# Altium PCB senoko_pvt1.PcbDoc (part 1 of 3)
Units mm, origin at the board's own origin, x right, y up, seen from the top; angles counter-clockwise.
Board outline 124.5 x 41 mm, 4 copper layers (Top Layer, Internal Plane 1, Internal Plane 2, Bottom Layer), stack 1.671 mm thick; 226 components, 139 nets, 1479 pads, 355 vias.
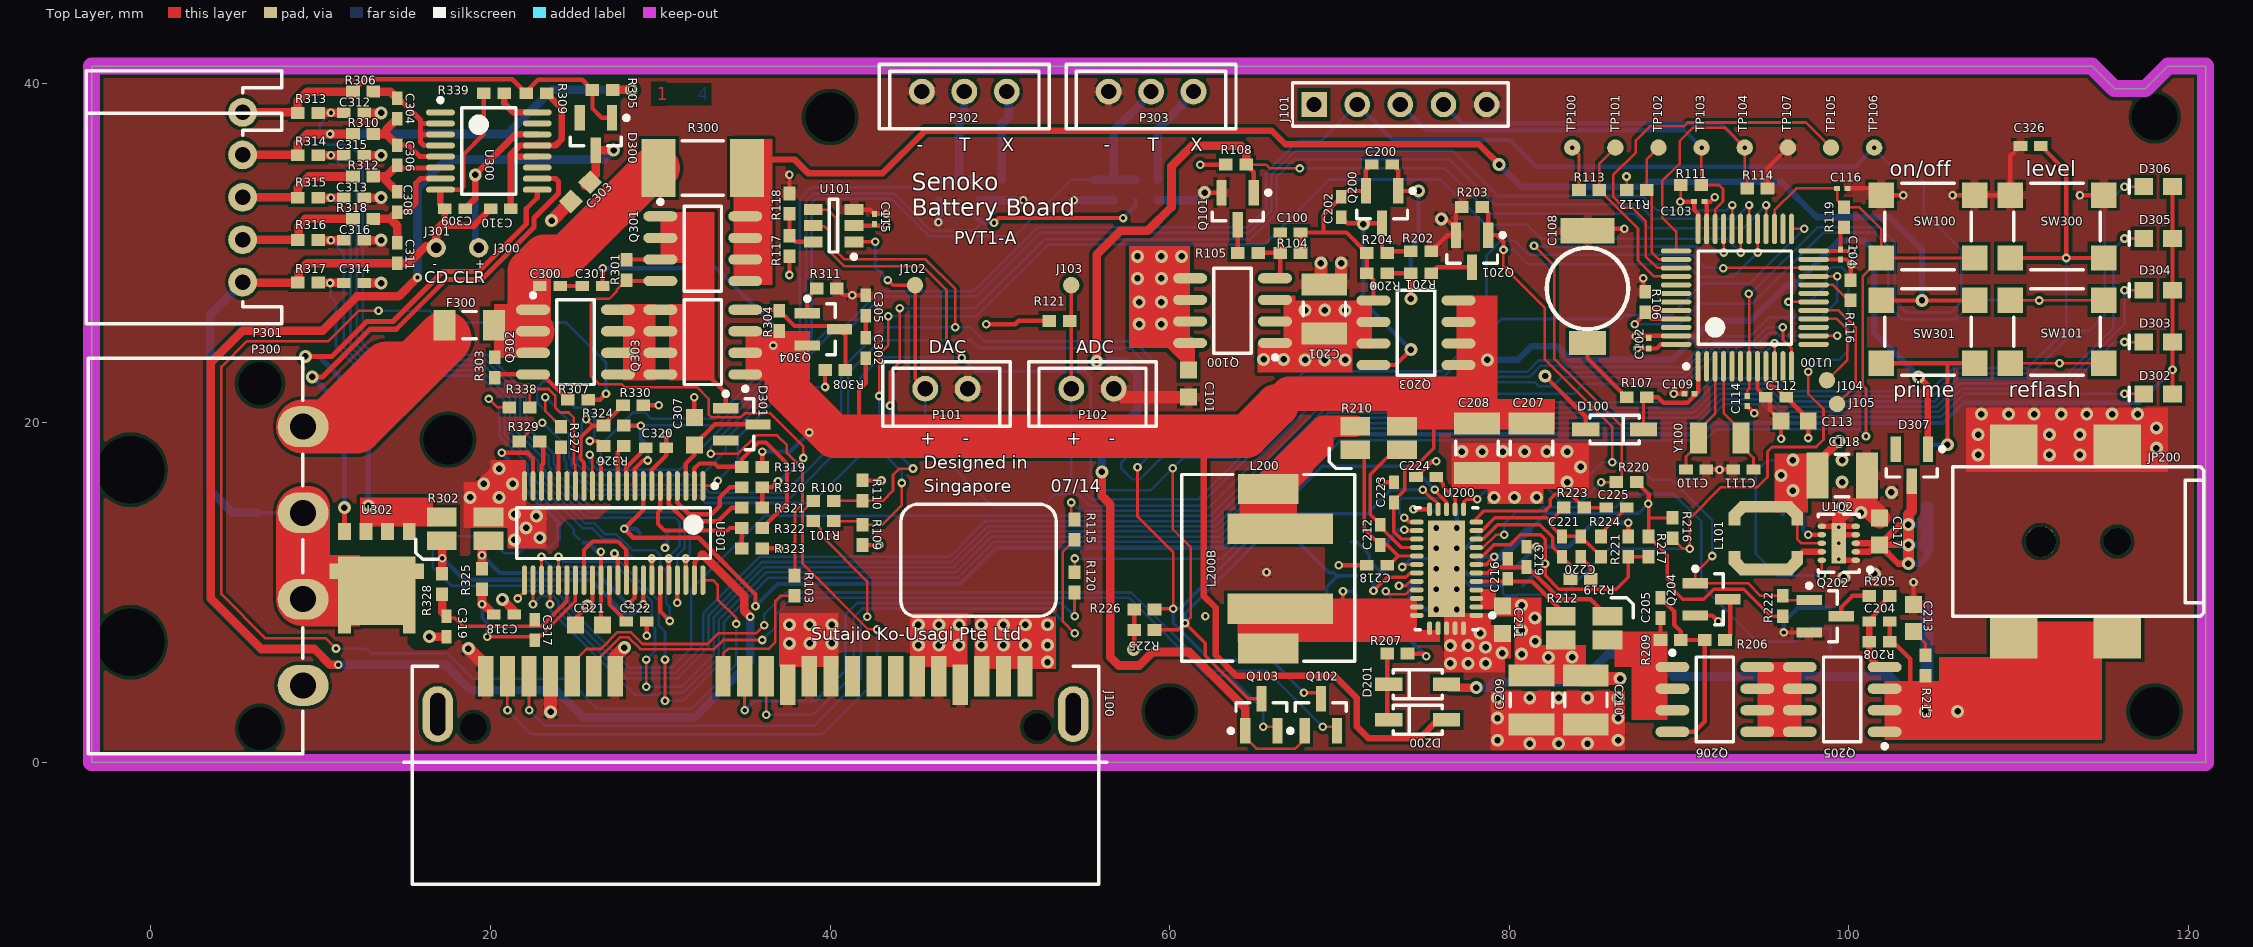
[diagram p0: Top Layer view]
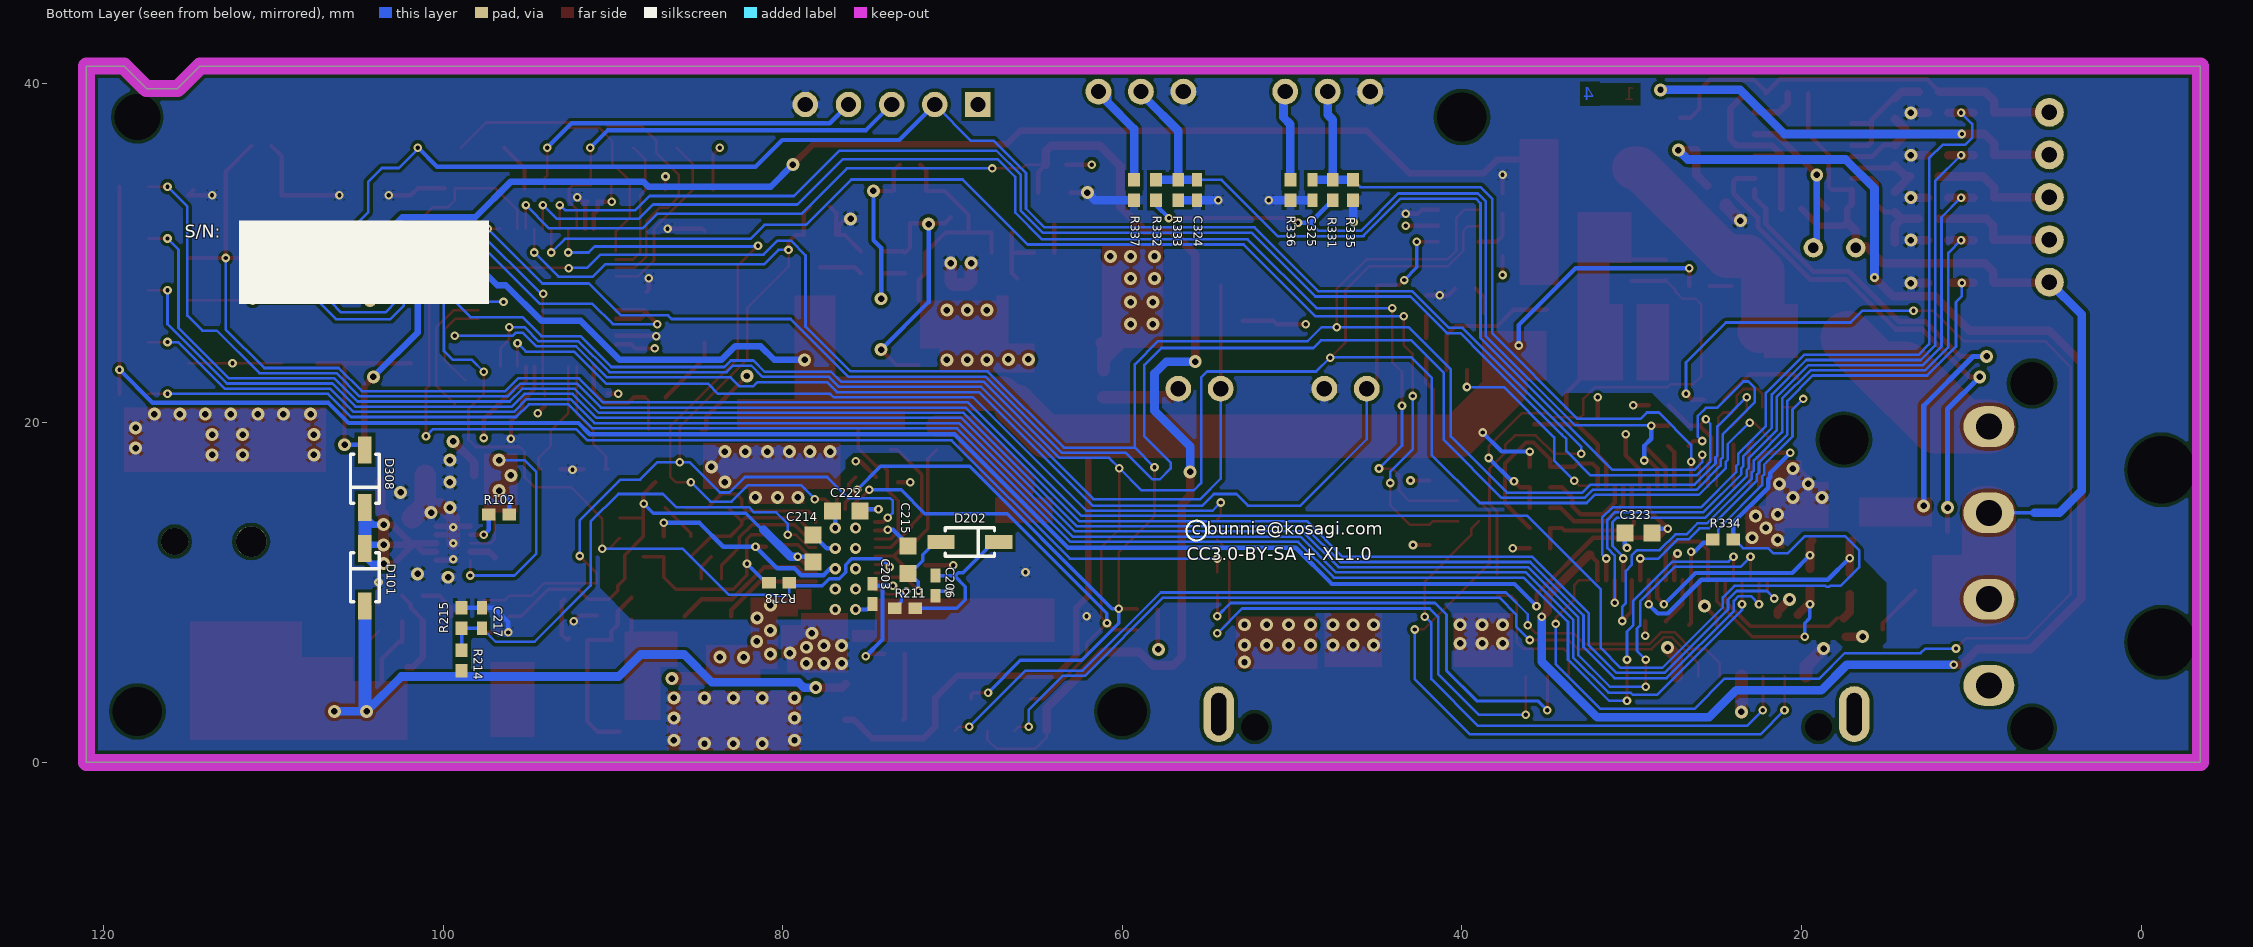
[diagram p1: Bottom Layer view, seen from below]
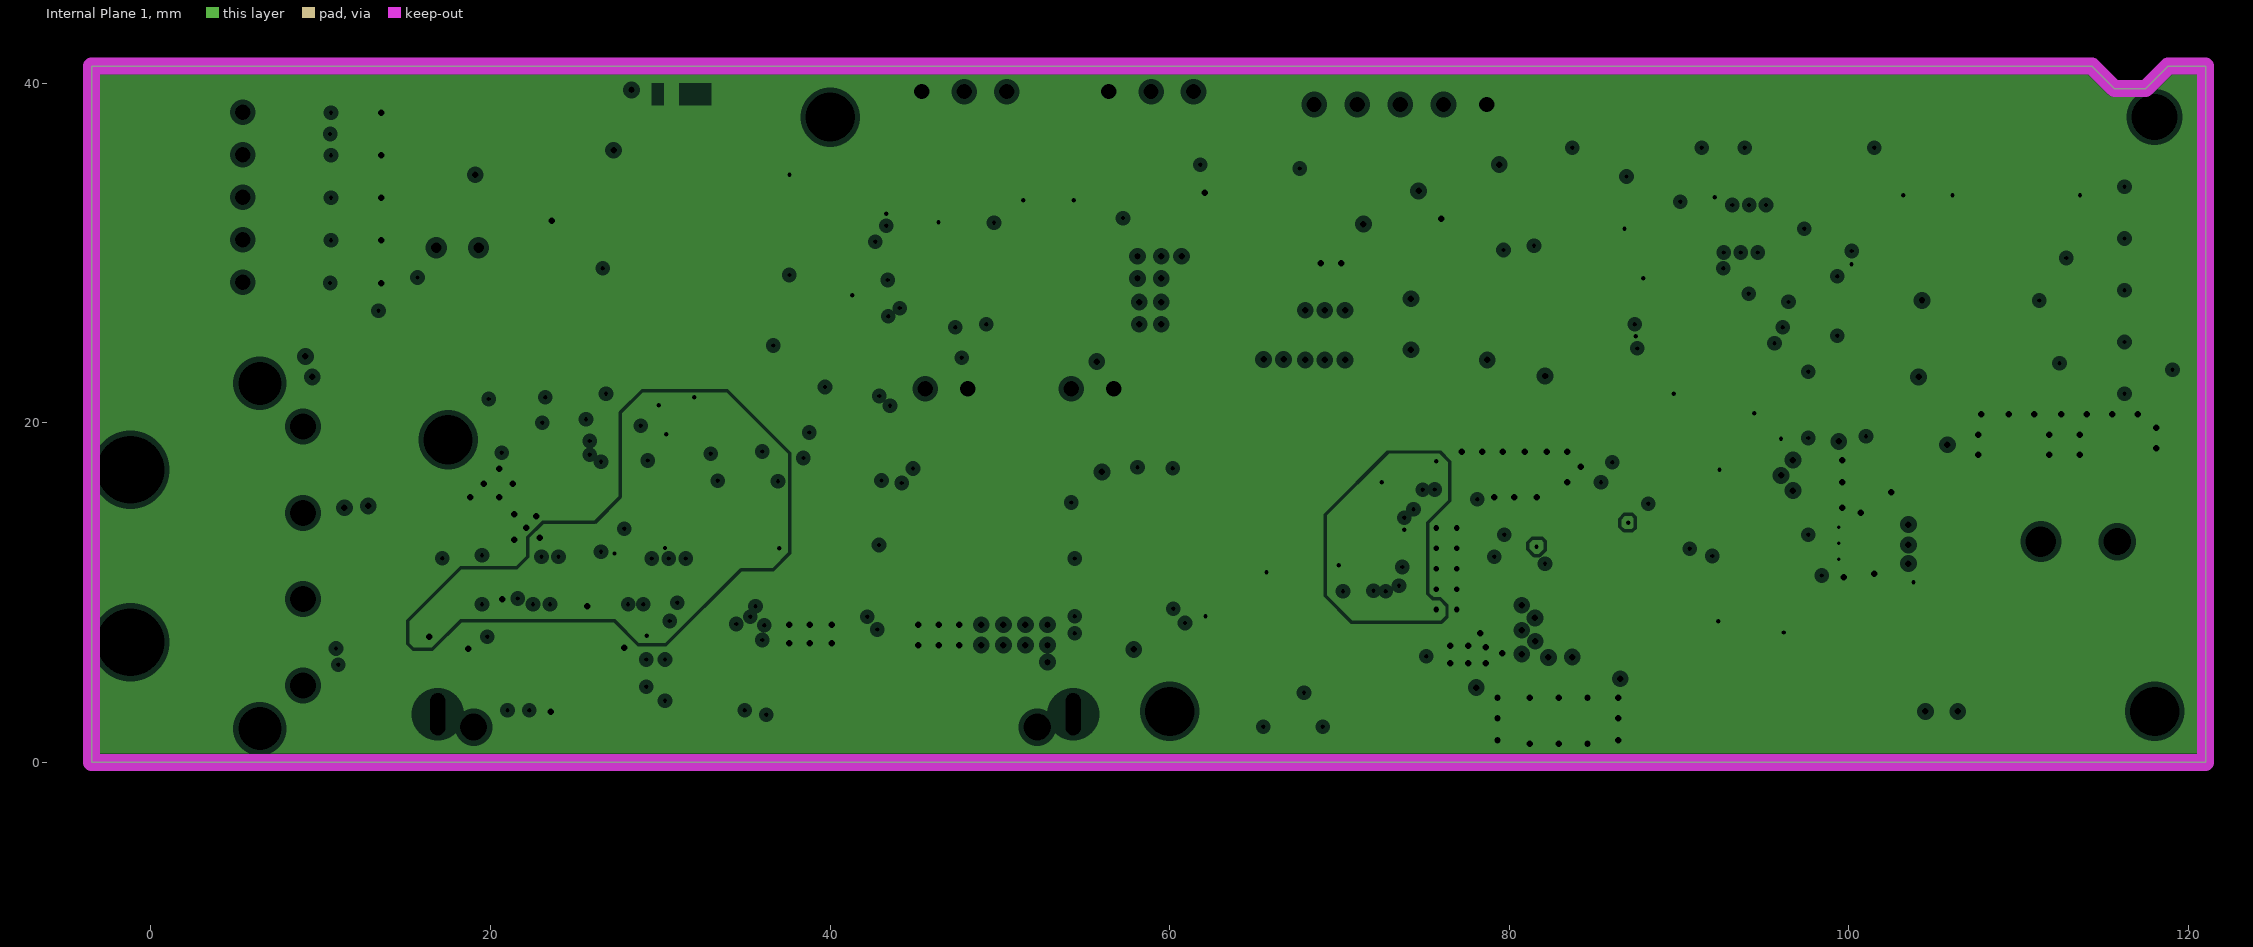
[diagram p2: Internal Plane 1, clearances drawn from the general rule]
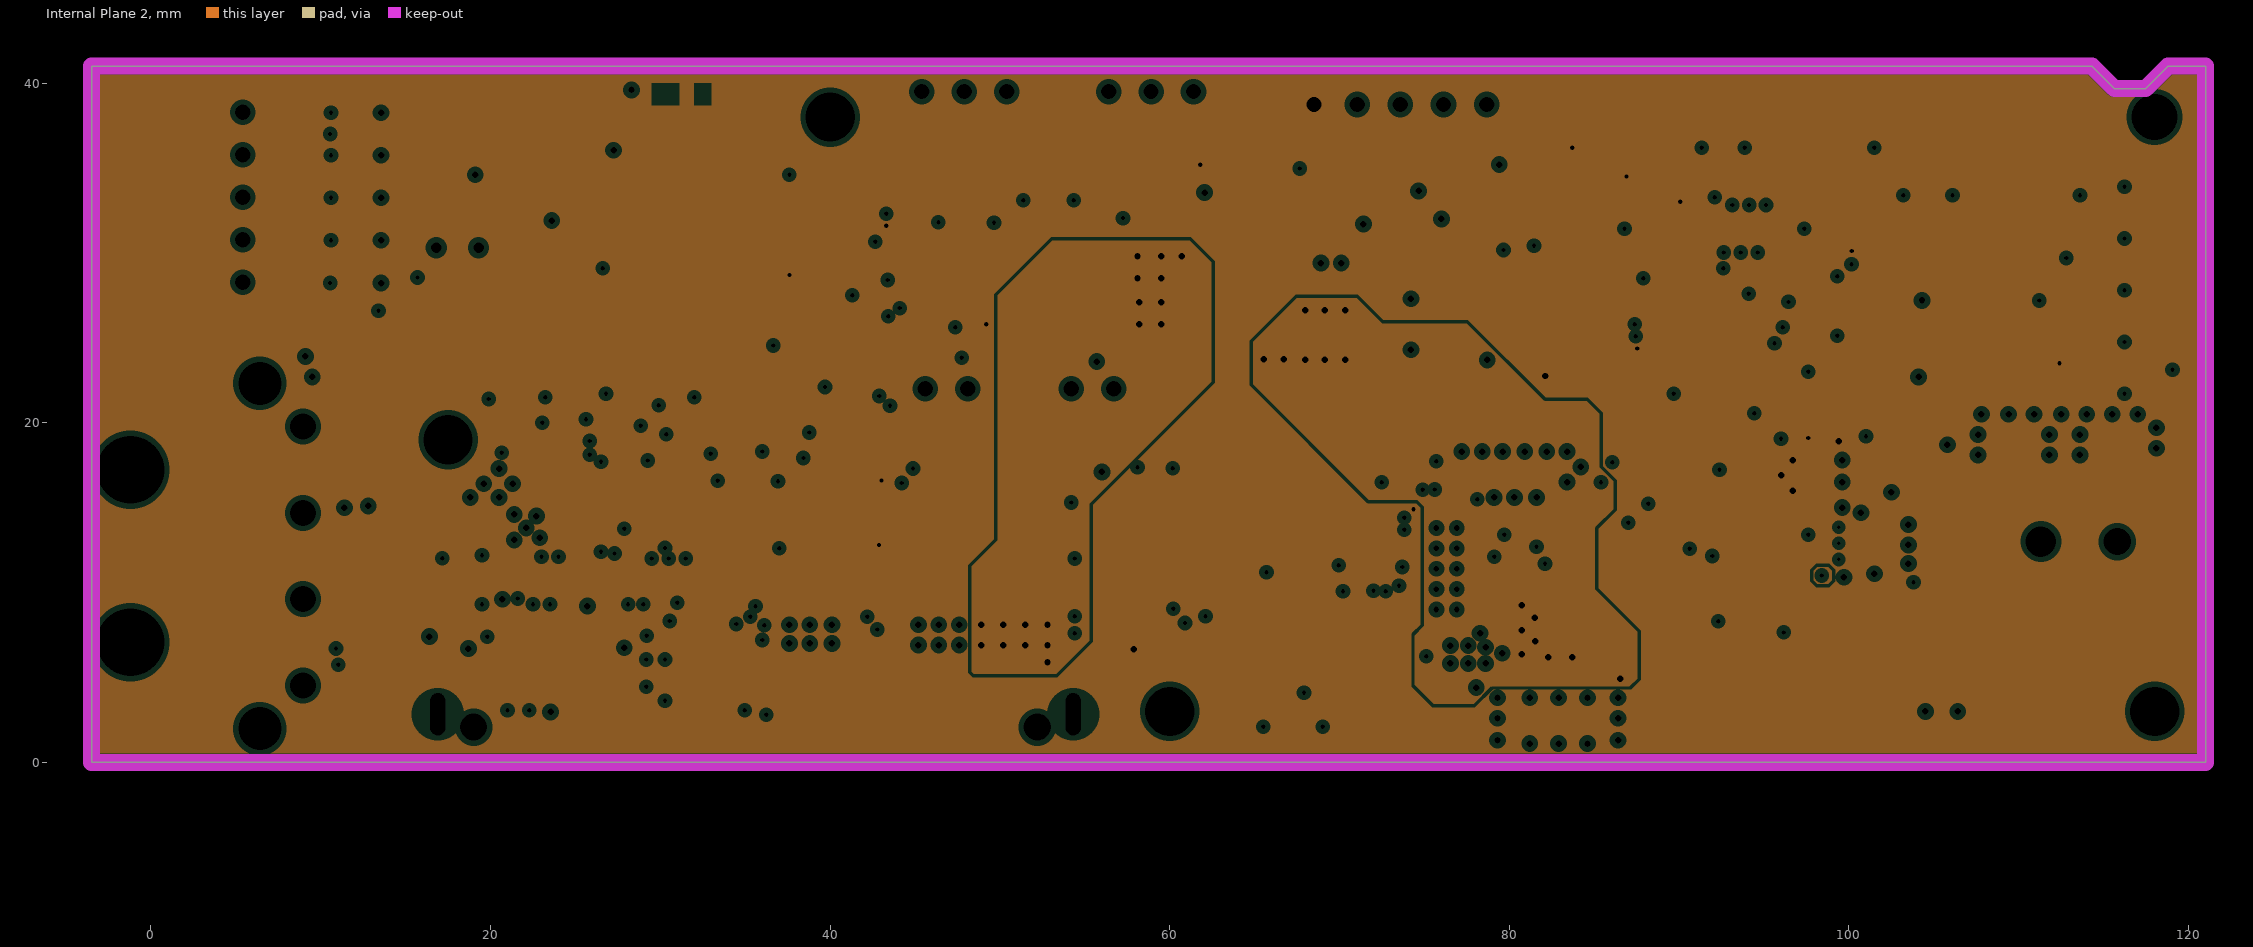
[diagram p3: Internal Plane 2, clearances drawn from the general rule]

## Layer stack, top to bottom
Top Solder: solder mask 0.0102, Solder Resist, Dk 3.5
Top Layer: signal copper 0.0356
Dielectric1: core 0.32, FR-4, Dk 4.8
Internal Plane 1: plane copper 0.0356, net GND
Dielectric2: prepreg 0.889, FR-4, Dk 4.8
Internal Plane 2: plane copper 0.0356, net (Multiple Nets)
Dielectric3: core 0.32, FR-4, Dk 4.8
Bottom Layer: signal copper 0.0356
Bottom Solder: solder mask 0.0102, Solder Resist, Dk 3.5

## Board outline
-3.5,0 -3.5,41 114.3,41 115.625,39.675 117.475,39.675 118.8,41 121,41 121,0

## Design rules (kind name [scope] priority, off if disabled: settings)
Clearance Clearance_poly [InPoly] p1: gap=0.203
Clearance Clearance_NPTH [PadIsPlated = 'False'] p2: gap=0.305
Clearance [All] p3: gap=0.152
ComponentClearance [All] p1 off: gap=0.254 collisioncheckmode=3 verticalgap=0.254 showdistances=FALSE
Height [All] p1 off: minheight=0 maxheight=25.4 prefheight=12.7
HoleSize [All] p1: absolutevalues=TRUE maxlimit=4.445 minlimit=0.025 maxpercent=80.000 minpercent=20.000
MinimumSolderMaskSliver [All] p1 off: minsoldermaskwidth=0.254
PlaneClearance PlaneClearance_M2.5 [(AsMM(HoleSize) = 2.9) or (AsMM(HoleSize) = 2.7)] p1: clearance=1.1
PlaneClearance [All] p2: clearance=0.305
PlaneConnect [All] p1: planeconnectstyle=Direct reliefexpansion=0.508 reliefentries=4 reliefconductorwidth=0.254 reliefairgap=0.254
PolygonConnect [All] p1: connectstyle=Relief reliefconductorwidth=0.508 reliefentries=4 polygonreliefangle="90 Angle" airgapwidth=0.152
RoomDefinition controller [InComponentClass('controller')] p1 off: confinementstyle=ConfineIn formatcopy=TRUE lockcomponents=FALSE outline -1.384,22.5 -3,22.5 -3,30.882 -1.384,30.882
RoomDefinition charger [InComponentClass('charger')] p2 off: confinementstyle=ConfineIn formatcopy=TRUE lockcomponents=FALSE outline -4.586,1.982 -1.8,1.982 -1.8,19 -4.586,19
RoomDefinition battery [InComponentClass('battery')] p3 off: confinementstyle=ConfineIn formatcopy=TRUE lockcomponents=FALSE outline -2.1,25.25 -1.75,25.25 -1.75,0.521 -2.1,0.521
RoutingVias [All] p1: holewidth=0.381 width=0.762 viastyle="Through Hole" minholewidth=0.254 minwidth=0.508 maxholewidth=0.381 maxwidth=0.762
SilkToSilkClearance [All] p1 off: silktosilkclearance=0.254
SilkToSolderMaskClearance SilkscreenOverComponentPads [IsPad] p1 off: minsilkscreentomaskgap=0.254 clearancetoexposedcopper=TRUE
SolderMaskExpansion [All] p1: expansion=0.07
Width [All] p1: maxlimit=5.08 minlimit=0.152 preferedwidth=0.203 minimp=50.000000 maximp=50.000000 favimp=50.000000
21 further rules are at their usual default settings.

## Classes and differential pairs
component class battery: C300 C301 C302 C303 C304 C305 C306 C307 C308 C309 C310 C311 C312 C313 C314 C315 C316 C317 C318 C319 C320 C321 C322 C323 C324 C325 C326 D300 D301 D302 D303 D304 D305 D306 D307 D308 F300 J300 J301 P300 P301 P302 P303 Q301 Q302 Q303 Q304 R300 R301 R302 R303 R304 R305 R306 R307 R308 R309 R310 R311 R312 R313 R314 R315 R316 R317 R318 R319 R320 R321 R322 R323 R324 R325 R326 R327 R328 R329 R330 R331 R332 R333 R334 R335 R336 R337 R338 R339 SW300 SW301 U300 U301 U302
component class charger: C200 C201 C202 C203 C204 C205 C206 C207 C208 C209 C210 C211 C212 C213 C214 C215 C216 C217 C218 C219 C220 C221 C222 C223 C224 C225 D200 D201 D202 JP200 L200 L200B Q200 Q201 Q202 Q203 Q204 Q205 Q206 R200 R201 R202 R203 R204 R205 R206 R207 R208 R209 R210 R211 R212 R213 R214 R215 R216 R217 R218 R219 R220 R221 R222 R223 R224 R225 R226 U200
component class controller: C100 C101 C102 C103 C104 C108 C109 C110 C111 C112 C113 C114 C115 C116 C117 C118 D100 D101 J100 J101 J102 J103 J104 J105 L101 N100 P101 P102 Q100 Q101 Q102 Q103 R100 R101 R102 R103 R104 R105 R106 R107 R108 R109 R110 R111 R112 R113 R114 R115 R116 R117 R118 R119 R120 R121 SW100 SW101 TP100 TP101 TP102 TP103 TP104 TP105 TP106 TP107 U100 U101 U102 Y100

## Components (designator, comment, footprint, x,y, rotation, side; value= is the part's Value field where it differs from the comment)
C100 "10nF, X7R, 50V 10%" CAPC1005N 67.1,31.2 r180 top
C101 "2.2uF, 25V, 10% X5R" CAPC1608N 61.1,22.3 r270 top
C102 "0.1uF, 6.3V, X5R" CAPC0603N_B 88.21,24.677 r90 top
C103 "0.1uF, 6.3V, X5R" CAPC0603N_B 91.18,33.02 r0 top
C104 "0.1uF, 6.3V, X5R" CAPC0603N_B 99.5,29.9 r270 top
C108 "0.06F 3.3V coin supercap" TAIYO_YUDEN_PAS414HR-VA5R 84.6,27.9 r90 top
C109 "0.1uF, 6.3V, X5R" CAPC0603N_B 90.614,21.707 r180 top
C110 "6.8pF, NP0" CAPC1005N 91,17.25 r0 top
C111 "6.8pF, NP0" CAPC1005N 93.775,17.25 r180 top
C112 "10nF, X7R, 50V 10%" CAPC1005N 95.7,21.5 r0 top
C113 "1.0uF, 25V, 20% X5R" CAPC1608N 96.8,20.1 r0 top
C114 "0.1uF, 6.3V, X5R" CAPC0603N_B 94.008,21.282 r270 top
C115 "0.1uF, 6.3V, X5R" CAPC0603N_B 42.6,32 r90 top
C116 "0.1uF, 6.3V, X5R" CAPC0603N_B 99.6,33.8 r180 top
C117 "2.2uF, 25V, 10% X5R" CAPC1608N 101.8,13.6 r90 top
C118 "22uF, 25V, X5R, 10%" CAPC3225N 99.6,16.9 r0 top
C200 "DNP" CAPC1005N 72.5,35.2 r180 top
C201 "22uF, 25V, X5R, 10%" CAPC3225N 69.1,26.7 r90 top
C202 "0.1uF, 25V, X5R" CAPC1005N 70.1,32.7 r270 top
C203 "0.1uF, 25V, X5R" CAPC1005N 74.7,9.925 r270 bottom
C204 "0.1uF, 25V, X5R" CAPC1005N 101.8,8.3 r0 top
C205 "10nF, X7R, 50V 10%" CAPC1005N 88.9,9.1 r270 top
C206 "0.1uF, 25V, X5R" CAPC1005N 71,10.4 r270 bottom
C207 "22uF, 25V, X5R, 10%" CAPC3225N 81.3,18.5 r270 top
C208 "22uF, 25V, X5R, 10% (DNP)" CAPC3225N 78.1,18.5 r270 top
C209 "22uF, 25V, X5R, 10%" CAPC3225N 81.3,3.675 r270 top
C210 "22uF, 25V, X5R, 10% (DNP)" CAPC3225N 84.5,3.675 r270 top
C211 "1.0uF, 25V, 20% X5R" CAPC1608N 79.6,8.4 r270 top
C212 "0.1uF, 25V, X5R" CAPC1005N 72.4,13.4 r270 top
C213 "2.2uF, 25V, 10% X5R" CAPC1608N 103.8,8.5 r90 top
C214 "1.0uF, 25V, 20% X5R" CAPC1608N 78.2,12.6 r90 bottom
C215 "1.0uF, 25V, 20% X5R" CAPC1608N 72.625,11.925 r90 bottom
C216 "0.1uF, 25V, X5R" CAPC1005N 79.9,11.4 r270 top
C217 "10nF, X7R, 50V 10%" CAPC1005N 97.7,8.5 r90 bottom
C218 "0.1uF, 25V, X5R" CAPC1005N 72.2,11.6 r0 top
C219 "0.1uF, 25V, X5R" CAPC1005N 81,12.1 r90 top
C220 "2.2nF, X7R, 10%" CAPC1005N 84.2,12.7 r90 top
C221 "51pF, NP0" CAPC1005N 83.1,12.7 r90 top
C222 "1.0uF, 25V, 20% X5R" CAPC1608N 76.25,14.8 r0 bottom
C223 "0.1uF, 25V, X5R" CAPC1005N 73.2,15.9 r270 top
C224 "100pF, NP0" CAPC1005N 75.1,16.8 r180 top
C225 "130pF, NP0" CAPC1005N 86.3,15 r180 top
C300 "0.1uF, 25V, X5R" CAPC1005N 23.5,28.05 r180 top
C301 "0.1uF, 25V, X5R" CAPC1005N 26,28.05 r180 top
C302 "0.1uF, 25V, X5R" CAPC1005N 42.1,24.4 r270 top
C303 "1.0uF, 25V, 20% X5R" CAPC1608N 25.3,33.6 r225 top
C304 "0.1uF, 25V, X5R" CAPC1005N 14.5,38.5 r270 top
C305 "0.1uF, 25V, X5R" CAPC1005N 42.1,26.9 r270 top
C306 "0.1uF, 25V, X5R" CAPC1005N 14.5,35.75 r270 top
C307 "1.0uF, 25V, 20% X5R" CAPC1608N 32,19.5 r90 top
C308 "0.1uF, 25V, X5R" CAPC1005N 14.5,33 r270 top
C309 "0.22uF, 25V, X5R" CAPC1005N 17.9,32.6 r180 top
C310 "0.1uF, 25V, X5R" CAPC1005N 20.6,32.6 r180 top
C311 "0.1uF, 25V, X5R" CAPC1005N 14.5,30 r270 top
C312 "0.1uF, 25V, X5R" CAPC1005N 11.95,38.25 r0 top
C313 "0.1uF, 25V, X5R" CAPC1005N 11.95,33.25 r0 top
C314 "0.1uF, 25V, X5R" CAPC1005N 11.95,28.225 r0 top
C315 "0.1uF, 25V, X5R" CAPC1005N 11.95,35.75 r0 top
C316 "0.1uF, 25V, X5R" CAPC1005N 11.95,30.75 r0 top
C317 "0.1uF, 25V, X5R" CAPC1005N 22.6,7.8 r90 top
C318 "0.1uF, 25V, X5R" CAPC1005N 20.8,8.7 r0 top
C319 "0.1uF, 25V, X5R" CAPC1005N 17.4,8 r270 top
C320 "0.1uF, 25V, X5R" CAPC1005N 29.75,18.525 r0 top
C321 "1.0uF, 25V, 20% X5R" CAPC1608N 25.8,8.1 r180 top
C322 "0.1uF, 25V, X5R" CAPC1005N 28.6,8.3 r0 top
C323 "10uF, 10V, X5R, 20%" CAPC1608N 29.6,13.5 r0 bottom
C324 "0.47uF, 16V, X5R" CAPC1005N 55.6,33.7 r270 bottom
C325 "0.47uF, 16V, X5R" CAPC1005N 48.8,33.7 r270 bottom
C326 "0.1uF, 25V, X5R" CAPC1005N 110.7,36.3 r180 top
D100 "BAT54T1G" SOD123 86.2,19.6 r0 top
D101 "BAT54T1G" SOD123 104.6,10.9 r90 bottom
D200 "BAT54T1G" SOD123 74.6,2.5 r180 top
D201 "BAT54T1G" SOD123 74.6,4.6 r180 top
D202 "BAT54T1G" SOD123 68.975,12.975 r180 bottom
D300 "BAS16" SOT23-3N 26.2,37 r270 top
D301 "BAS16" SOT23-3N 34.8,19.9 r0 top
D302 "APT1608SGC green" CD1608-0603 118.2,21.7 r180 top
D303 "APT1608SGC green" CD1608-0603 118.2,24.75 r180 top
D304 "APT1608SGC green" CD1608-0603 118.2,27.8 r180 top
D305 "APT1608SGC green" CD1608-0603 118.2,30.85 r180 top
D306 "APT1608SGC green" CD1608-0603 118.2,33.9 r180 top
D307 "BAS16" SOT23-3N 103.7,17.5 r270 top
D308 "BAT54T1G" SOD123 104.6,16.7 r270 bottom
F300 "Littlefuse 0437007.WR 7A 35V Fast Blow" RESC3216N 18.75,25.75 r0 top
J100 "MOLEX 47018-2000 female" SATA_MOLEX_47018_2000 35.6,2.075 r0 top
J101 "Male 2.54mm 5x1 header (DNP)" HDR1X5 68.5,38.74 r0 top
J102 "test point (DNP)" TP_SMT_38mil 45,28.1 r90 top
J103 "test point (DNP)" TP_SMT_38mil 54.2,28.1 r90 top
J104 "test point (DNP)" TP_SMT_38mil 98.7,22.5 r180 top
J105 "test point (DNP)" TP_SMT_38mil 99.3,21.1 r180 top
J300 "test point (DNP)" TP_HOLE 19.3,30.3 r90 top
J301 "test point (DNP)" TP_HOLE 16.8,30.3 r90 top
JP200 "2.1mm x 5.5mm DC jack" CUI_PJ_002AH_SMT 111.3,13 r180 top
L101 "10uH LPS4018-103" COILCRAFT_LPS4018 95.1,13.2 r90 top
L200 "3.3uH, MSS1260-332NL (DNP)" COILCRAFT_MSS1048 65.8,6.7 r0 top
L200B "3.3uH, XAL7030-322MEC" COILCRAFT_XAL7030 66.5,11.4 r90 top
P101 "JST B2B-EH-A" JST_B2B_EH_A 45.6,22 r0 top
P102 "JST B2B-EH-A" JST_B2B_EH_A 54.2,22 r0 top
P300 "Molex 15-24-4441" MOLEX_15-24-4441 -1.2,12.15 r90 top
P301 "JST S4B-XH-A" JST_S5B-XH-A_OPT4 5.4,34.525 r90 top
P302 "JST B3B-EH-A" JST_B3B_EH_A 45.4,39.5 r0 top
P303 "JST B3B-EH-A" JST_B3B_EH_A 56.4,39.5 r0 top
Q100 "Si4435DY" SOIC127P600-8AN 63.7,26.6 r180 top
Q101 "BSS138" SOT23-3N 64,32.6 r270 top
Q102 "BSS138" SOT23-3N 68.9,2.8 r90 top
Q103 "BSS138" SOT23-3N 65.4,2.8 r90 top
Q200 "FDN304P" SOT23-3N 72.5,32.7 r270 top
Q201 "BSS138" SOT23-3N 77.8,30.1 r270 top
Q202 "BSS138" SOT23-3N 98.6,8.6 r0 top
Q203 "Si4435DY" SOIC127P600-8AN 74.5,25.3 r0 top
Q204 "BSS138" SOT23-3N 91.9,9.6 r0 top
Q205 "Si4435DY" SOIC127P600-8AN 99.6,3.7 r180 top
Q206 "Si4435DY" SOIC127P600-8AN 92.1,3.7 r0 top
Q301 "Si4435DY" SOIC127P600-8AN 32.5,30.25 r0 top
Q302 "FDS6690A" SOIC127P600-8AN 25,24.75 r0 top
Q303 "FDS6690A" SOIC127P600-8AN 32.5,24.75 r180 top
Q304 "BSS138" SOT23-3N 39.6,25.5 r0 top
R100 "330, 1%" RESC1005N 39.6,15.4 r180 top
R101 "330, 1%" RESC1005N 39.6,14.2 r180 top
R102 "100k, 1%" RESC1005N 96.7,14.6 r0 bottom
R103 "330, 1%" RESC1005N 37.9,10.4 r270 top
R104 "10k, 1%" RESC1005N 67.1,30 r0 top
R105 "10k, 1%" RESC1005N 64.6,30 r0 top
R106 "47k, 1%" RESC1005N 88,27.1 r270 top
R107 "1k, 1%" RESC1005N 87.5,21.5 r0 top
R108 "100k, 1%" RESC1005N 63.9,35.2 r0 top
R109 "47k, 1%" RESC1005N 41.9,13.4 r270 top
R110 "47k, 1%" RESC1005N 41.9,16 r90 top
R111 "10k, 1%" RESC1005N 90.7,34 r180 top
R112 "10k, 1%" RESC1005N 87.5,33.7 r180 top
R113 "10k, 1%" RESC1005N 84.7,33.7 r180 top
R114 "10k, 1%" RESC1005N 94.6,33.8 r180 top
R115 "330, 1%" RESC1005N 54.4,13.7 r270 top
R116 "10k, 1%" RESC1005N 100.1,27.8 r270 top
R117 "10k, 1% (DNP)" RESC1005N 37.6,30.4 r90 top
R118 "10k, 1%" RESC1005N 37.6,32.9 r90 top
R119 "47k, 1%" RESC1005N 99.7,32.1 r270 top
R120 "330, 1%" RESC1005N 54.4,10.6 r270 top
R121 "4.7k, 1%" RESC1005N 53.5,26 r180 top
R200 "10k, 1%" RESC1005N 72.2,28.8 r0 top
R201 "20k, 1%" RESC1005N 74.8,28.8 r0 top
R202 "100k, 1%" RESC1005N 74.8,30.1 r0 top
R203 "1M, 1%" RESC1005N 77.8,32.7 r0 top
R204 "100k, 1%" RESC1005N 72.2,30 r0 top
R205 "10k, 1%" RESC1005N 101.8,9.8 r180 top
R206 "10k, 1%" RESC1005N 92.1,7.2 r180 top
R207 "10 ohm, 1%" RESC1005N 73.4,6.4 r0 top
R208 "10k, 1%" RESC1005N 101.8,7.1 r180 top
R209 "10k, 1%" RESC1005N 89.5,7.2 r0 top
R210 "0.010 ohm, 1% kelvin, 50ppm" OHMITE_LVK_1206_KELVIN 72.3,19.1 r0 top
R211 "3.9 ohm, 5%" RESC1005N 72.8,9.075 r180 bottom
R212 "0.010 ohm, 1% kelvin, 50ppm" OHMITE_LVK_1206_KELVIN 84.4,7.9 r180 top
R213 "3.9 ohm, 5%" RESC1005N 104.5,5.7 r90 top
R214 "316k, 1%" RESC1005N 98.9,6 r90 bottom
R215 "66.5k, 1%" RESC1005N 98.9,8.5 r90 bottom
R216 "10k, 1%" RESC1005N 89.6,13.8 r270 top
R217 "200k, 1%" RESC1005N 88.2,12.7 r270 top
R218 "1.4M, 1%" RESC1005N 80.2,10.575 r180 bottom
R219 "7.5k, 1%" RESC1005N 84.2,10.8 r180 top
R220 "10k, 1%" RESC1005N 86.9,16.5 r180 top
R221 "49.9k, 1%" RESC1005N 87,12.7 r90 top
R222 "10k, 1%" RESC1005N 96.1,9.2 r90 top
R223 "200k, 1%" RESC1005N 83.8,15 r0 top
R224 "20k, 1%" RESC1005N 85.4,12.7 r90 top
R225 "10k, 1%" RESC1005N 58.5,7.8 r0 top
R226 "10k, 1%" RESC1005N 58.5,9 r0 top
R300 "300, 5%, 1W" RESC6432N 32.5,35 r180 top
R301 "1M, 1%" RESC1005N 28,29 r90 top
R302 "0.010 ohm, 1% kelvin, 50ppm" OHMITE_LVK_1206_KELVIN 18.5,13.75 r0 top
R303 "3.01M, 1%" RESC1005N 20.25,23.25 r270 top
R304 "3.01M, 1%" RESC1005N 37,26 r270 top
R305 "0 ohm" RESC1005N 26.6,39.6 r180 top
R306 "1k, 1%" RESC1005N 12.5,39.5 r0 top
R307 "5.1k, 1%" RESC1005N 25.15,21.35 r0 top
R308 "5.1k, 1%" RESC1005N 40.3,23.1 r180 top
R309 "1k, 1%" RESC1005N 22.7,39.4 r0 top
R310 "1k, 1%" RESC1005N 12.5,37 r0 top
R311 "1M, 1%" RESC1005N 39.8,27.9 r0 top
R312 "1k, 1%" RESC1005N 12.5,34.5 r0 top
R313 "100, 1%" RESC1005N 9.25,38.25 r0 top
R314 "100, 1%" RESC1005N 9.25,35.75 r0 top
R315 "100, 1%" RESC1005N 9.25,33.25 r0 top
R316 "100, 1%" RESC1005N 9.25,30.75 r0 top
R317 "100, 1%" RESC1005N 9.25,28.25 r0 top
R318 "1k, 1%" RESC1005N 12.5,32 r0 top
R319 "1k, 1%" RESC1005N 35.4,17.4 r180 top
R320 "5.1k, 1%" RESC1005N 35.4,16.2 r180 top
R321 "5.1k, 1% (DNP)" RESC1005N 35.4,15 r180 top
R322 "100k, 1% (DNP)" RESC1005N 35.4,13.8 r0 top
R323 "100k, 1%" RESC1005N 35.4,12.6 r0 top
R324 "100k, 1%" RESC1005N 27.25,19.825 r180 top
R325 "100, 1%" RESC1005N 19.5,10.8 r90 top
R326 "0 ohm" RESC1005N 27.25,18.625 r180 top
R327 "0 ohm" RESC1005N 24.15,19.15 r90 top
R328 "100, 1%" RESC1005N 17.15,10.5 r90 top
R329 "0 ohm" RESC1005N 22.3,18.9 r180 top
R330 "1k, 1%" RESC1005N 28.4,21.025 r0 top
R331 "8.45k, 1%" RESC1005N 47.6,33.7 r270 bottom
R332 "8.45k, 1%" RESC1005N 58,33.7 r270 bottom
R333 "61.9k, 1%" RESC1005N 56.7,33.7 r90 bottom
R334 "100k, 1%" RESC1005N 24.625,13.125 r0 bottom
R335 "61.9k, 1%" RESC1005N 46.4,33.7 r90 bottom
R336 "10k, 1%" RESC1005N 50.1,33.7 r90 bottom
R337 "10k, 1%" RESC1005N 59.3,33.7 r90 bottom
R338 "5.1k, 1%" RESC1005N 21.7,20.9 r0 top
R339 "1k, 1% (DNP)" RESC1005N 20.2,39.4 r180 top
SW100 "TL3342F160QG/TR" SWITCH_TS-1187A 101.9,29.7 r90 top
SW101 "TL3342F160QG/TR" SWITCH_TS-1187A 109.5,23.5 r90 top
SW300 "TL3342F160QG/TR" SWITCH_TS-1187A 115,33.4 r270 top
SW301 "TL3342F160QG/TR" SWITCH_TS-1187A 107.4,27.2 r270 top
TP100 "38mil SMT pad" TP_SMT_38mil 83.7,36.2 r90 top
TP101 "38mil SMT pad" TP_SMT_38mil 86.24,36.2 r90 top
TP102 "38mil SMT pad" TP_SMT_38mil 88.78,36.2 r90 top
TP103 "38mil SMT pad" TP_SMT_38mil 91.32,36.2 r90 top
TP104 "38mil SMT pad" TP_SMT_38mil 93.86,36.2 r90 top
TP105 "38mil SMT pad" TP_SMT_38mil 98.94,36.2 r90 top
TP106 "38mil SMT pad" TP_SMT_38mil 101.48,36.2 r90 top
TP107 "38mil SMT pad" TP_SMT_38mil 96.4,36.2 r90 top
U100 "STM32F101C8T6" TSQFP50P900X900-48N 93.867,27.364 r90 top
U101 "DAC081C081CIMK" SOT26A-6N 40.2,31.6 r180 top
U102 "TPS62177DQCT" TI_DQC_R_PWSON_N10 99.4,12.9 r180 top
U200 "BQ24765RUV" TI_R-PVQFN-N34 76.3,11.4 r180 top
U300 "bq77PL157A4225" TSOP65P640-16AN 19.9,36 r0 top
U301 "BQ20Z95DBT" TSSOP50P640-44N 27.25,13.5 r270 top
U302 "NTMFS4C35NT1G" ONSEMI_DFN5_5x6_1.27P 13.3,10.8 r0 top
Y100 "Abracon ABS07-120-32.768KHZ-T 6pF CL" ABS07-120 92.4,19.1 r180 top

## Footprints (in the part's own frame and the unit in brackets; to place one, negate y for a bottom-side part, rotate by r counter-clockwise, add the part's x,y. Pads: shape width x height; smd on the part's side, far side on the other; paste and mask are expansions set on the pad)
ABS07-120 [mm] "32.768kHz SMD low-ESR"
  rect 1x1.8 smd: 1(-1.25,0) 2(1.25,0)
  body extent -1.6,-0.75 1.6,0.75, height 0.9
CAPC0603N_B [mm] "Chip Capacitor, 2-Leads, Body 0.6x0.3mm, IPC Medium Density"
  rect 0.35x0.3 smd mask+0.07: 1(-0.3,0) 2(0.3,0)
  body extent -0.32,-0.16 0.32,0.17, height 0.33
CAPC1005N [mm] "Chip Capacitor, Body 1.0x0.5mm, IPC Medium Density"
  rect 0.8x0.6 smd: 1(-0.6,0) 2(0.6,0)
  body extent -0.55,-0.3 0.55,0.3, height 0.6
CAPC1608N [mm] "Chip Capacitor, Body 1.6x0.8mm, IPC Medium Density"
  rect 1x1 smd: 1(-0.8,0) 2(0.8,0)
  body extent -0.88,-0.48 0.87,0.48, height 0.85
CAPC3225N [mm] "Chip Capacitor, Body 3.2x2.5mm, IPC Medium Density"
  rect 1.3x2.7 smd: 1(-1.45,0) 2(1.45,0)
  silkscreen extent -0.4,-1.25 0.4,1.25, body extent -1.7,-1.35 1.7,1.35, height 1.35
CD1608-0603 [mm] "Chip Diode; Body 1.6 x 0.8 mm (LxW typ)"
  rect 1.1x1 smd: 1(-0.85,0) 2(0.85,0)
  silkscreen extent 1.7,-0.4 1.7,0.4
COILCRAFT_LPS4018 [mm] "Coilcraft SMT power inductor, shielded, high current"
  rect 0.7x3.124 smd mask+0.07: 1(-1.85,0) 2(1.85,0)
  rect 0.7x1 smd rot 135 mask+0.07: 1(-1.6,1.6) 2(1.6,-1.6)
  rect 0.7x1 smd rot 45 mask+0.07: 1(-1.6,-1.6) 2(1.6,1.6)
  rect 0.75x0.7 smd mask+0.07: 1(-1.125,1.85) 1(-1.125,-1.85) 2(1.125,1.85) 2(1.125,-1.85)
  body extent -2.05,-2.05 2.05,2.05, height 1.8
COILCRAFT_MSS1048 [mm] "Coilcraft shielded power inductor"
  rect 3.56x1.78 smd mask+0.075: 1(0,0) 2(0,9.4)
  silkscreen extent -5.1,-0.75 5.1,10.25
COILCRAFT_XAL7030 [mm] "XAL7030 inductor"
  rect 1.78x6.22 smd: 1(-2.36,0) 2(2.36,0)
  body extent -4,-4 4,4, height 3.1
CUI_PJ_002AH_SMT [mm] "SMT 2.1mmx5.5mm ID (P-5) connector"
  round 1.6 hole 1.6 unplated: 0(-4.5,0)
  round 1.8 hole 1.8 unplated: 0(0,0)
  rect 2.8x2.4 smd: 1(-4.5,5.7) 1(1.6,5.7) 2(-4.5,-5.7) 3(1.6,-5.7)
  silkscreen extent -9.6,-4.4 5.2,4.4, body extent -9.5,-6.3 5.3,6.3, height 11.19
HDR1X5 [mm] "Connector; Header; 5 Position"
  rect 1.5x1.5 hole 0.9: 1(0,0)
  round 1.5 hole 0.9: 2(2.54,0) 3(5.08,0) 4(7.62,0) 5(10.16,0)
  silkscreen extent -1.27,-1.27 11.43,1.27
JST_B2B_EH_A [mil] "2-pin 2.5mm low cost connector"
  round 60 hole 35.43: 1(0,0) 2(98.42,0)
  silkscreen extent -98,-87 197,63, body extent -98,-87 197,63, height 236
JST_B3B_EH_A [mil] "3-pin 2.5mm low cost connector"
  round 60 hole 35.43: 1(0,0) 2(98.43,0) 3(196.85,0)
  silkscreen extent -98,-87 295,63, body extent -98,-87 295,63, height 236
JST_S5B-XH-A_OPT4 [mm] "JST 5-pin 2.5mm RA male connector with 4-pin stuff option"
  round 1.7 hole 0.9 mask+0.07: 1(3.75,0) 2(1.25,0) 3(-1.25,0) 4(-3.75,0) 5(-6.25,0)
  silkscreen extent -8.7,-2.3 6.2,9.2, body extent -8.7,-2.3 6.2,9.2, height 6.1
MOLEX_15-24-4441 [mm] "4-pin classic PC disk drive power connector, RA"
  round 2.4 hole 2.54 unplated mask+0.07: 0(-10.16,-7.62) 0(10.16,-7.62)
  round 2.4 hole 3.99 unplated mask+0.07: 0(-5.08,0) 0(5.08,0)
  oval 2.4x3 hole 1.52 mask+0.07: 1(7.62,-10.16) 2(2.54,-10.16) 3(-2.54,-10.16) 4(-7.62,-10.16)
  silkscreen extent -11.65,-10.15 11.65,2.5, body extent -11.62,-10.88 11.65,2.78, height 8.79
OHMITE_LVK_1206_KELVIN [mm] "4-terminal kelvin sense resistor, 1206 package"
  rect 1.75x1.1 smd mask+0.07: 1(-1.375,-0.7) 2(-1.375,0.7) 3(1.375,0.7) 4(1.375,-0.7)
  silkscreen extent -2.9,-1.8 -1.6,-0.6, body extent -1.6,-0.8 1.6,0.8, height 0.65
ONSEMI_DFN5_5x6_1.27P [mm] "DFN 5x6 package, power FET"
  rect 0.75x1 smd mask+0.07: 1(1.905,2.795) 2(0.635,2.795) 3(-0.635,2.795) 4(-1.905,2.795)
  rect 0.495x0.905 smd mask+0.07: 5(-2.528,0.453) 8(2.528,0.453)
  rect 0.75x0.475 smd mask+0.07: 6(-1.905,-2.963) 7(1.905,-2.963)
  rect 4.56x4.055 smd paste-3 mask+0.07: 9(0,-0.697)
  body extent -2.42,-3 2.48,2.8, height 1.1
RESC1005N [mm] "Chip Resistor, Body 1.1x0.5mm, IPC Medium Density"
  rect 0.8x0.7 smd: 1(-0.6,0) 2(0.6,0)
  body extent -0.55,-0.3 0.55,0.3, height 0.4
RESC3216N [mm] "Chip Resistor, Body 3.2x1.6mm, IPC Medium Density"
  rect 1.3x1.8 smd: 1(-1.45,0) 2(1.45,0)
  silkscreen extent -0.4,-0.8 0.4,0.8, body extent -1.68,-0.87 1.68,0.87, height 0.71
RESC6432N [mm] "Chip Resistor, Body 6.4x3.2mm, IPC Medium Density"
  rect 2x3.4 smd: 1(-2.6,0) 2(2.6,0)
  silkscreen extent -1.2,-1.6 1.2,1.6, body extent -3.3,-1.7 3.3,1.7, height 1.2
SATA_MOLEX_47018_2000 [mm] "SATA docking connector, top mount type"
  oval 1.8x3.3 hole 0.9 slot 2.5 at 90 deg mask+0.07: 0(-18.71,0.76) 0(18.71,0.76)
  round 1 hole 1.6 unplated mask+0.07: 0(-16.595,0) 0(16.595,0)
  rect 0.9x2.4 smd mask+0.07: 1(15.875,3) 2(14.605,3) 3(13.335,3) 4(12.065,2.5) 5(10.795,3) 6(9.525,3) 7(8.255,3) 8(6.985,3) 9(5.715,3) 10(4.445,3) 11(3.175,3) 12(1.905,2.5) 13(0.635,3) 14(-0.635,3) 15(-1.905,3) 16(-8.255,3) 17(-9.525,3) 18(-10.795,3) 19(-12.065,3) 20(-13.335,3) 21(-14.605,3) 22(-15.875,3)
  silkscreen extent -20.73,-9.25 20.7,3.57, body extent -20.19,-9.28 20.24,3.59, height 4.35
SOD123 [mm] "SOD-123; 2 Leads; Body 2.7 x 1.6 mm, (LxW)"
  rect 1.6x0.8 smd: 1(-1.7,0) 2(1.7,0)
  silkscreen extent -1.45,-0.85 1.45,0.85
SOIC127P600-8AN [mm] "SOIC, 8-Leads, Body 4.9x3.9mm, Pitch 1.27mm, IPC Medium Density"
  oval 2x0.6 smd: 1(-2.5,1.905) 2(-2.5,0.635) 3(-2.5,-0.635) 4(-2.5,-1.905) 5(2.5,-1.905) 6(2.5,-0.635) 7(2.5,0.635) 8(2.5,1.905)
  silkscreen extent -2.63,-2.5 1.1,2.88, body extent -2,-2.5 2,2.5, height 2.72
SOT23-3N [mm] "SOT23, 3-Leads, Body 2.9x1.3mm, Pitch 0.95mm, Lead Span 2.5mm, IPC Medium Density"
  rect 1.5x0.6 smd: 1(-0.95,0.95) 2(-0.95,-0.95) 3(0.95,0)
  silkscreen extent -1.07,-1.5 0.7,1.93, body extent -0.7,-1.5 0.7,1.5, height 1.1
SOT26A-6N [mm] "SOT23, 6-Leads, Body 2.9x1.7mm, Pitch 0.95mm, Lead Span 2.8mm, IPC Medium Density"
  rect 1.1x0.65 smd: 1(-1.2,0.95) 2(-1.2,0) 3(-1.2,-0.95) 4(1.2,-0.95) 5(1.2,0) 6(1.2,0.95)
  silkscreen extent -1.33,-1.55 0.25,1.95, body extent -0.9,-1.55 0.9,1.55, height 1.45
SWITCH_TS-1187A [mm] "TS-1187A tact switch, Chi Fung Electronics"
  rect 1.5x1.5 smd mask+0.07: 1(0,0) 2(0,-5.5) 3(3.7,0) 4(3.7,-5.5)
  silkscreen extent -0.7,-5.3 4.4,-0.2, body extent -0.7,-5.3 4.4,-0.2, height 1.6
TAIYO_YUDEN_PAS414HR-VA5R [mm] "Taiyo Yuden Supercap"
  rect 1.4x2.2 smd: 1(-3.2,0)
  rect 1.5x3.2 smd: 2(3.4,0)
  silkscreen extent -2.4,-2.4 2.4,2.4, body extent -2.36,-2.39 2.42,2.4, height 1.4
TI_DQC_R_PWSON_N10 [mm] "TI Plastic small outline no-lead 10 pins with power pad"
  oval 0.5x0.3 smd mask+0.07: 1(-1,1) 2(-1,0.5) 3(-1,0) 4(-1,-0.5) 5(-1,-1) 6(1,-1) 7(1,-0.5) 8(1,0) 9(1,0.5) 10(1,1)
  rect 0.84x2.4 smd mask+0.07: 11(0,0)
  silkscreen extent -1.98,-1.7 1.2,1.7, body extent -1.05,-1.55 1.05,1.55, height 0.8
TI_R-PVQFN-N34 [mm] "34-pin QFN (from TI datasheet)"
  oval 0.8x0.3 smd mask+0.07: 1(-1.75,2.75) 2(-1.75,2.25) 3(-1.75,1.75) 4(-1.75,1.25) 5(-1.75,0.75) 6(-1.75,0.25) 7(-1.75,-0.25) 8(-1.75,-0.75) 9(-1.75,-1.25) 10(-1.75,-1.75) 11(-1.75,-2.25) 12(-1.75,-2.75) 18(1.75,-2.75) 19(1.75,-2.25) 20(1.75,-1.75) 21(1.75,-1.25) 22(1.75,-0.75) 23(1.75,-0.25) 24(1.75,0.25) 25(1.75,0.75) 26(1.75,1.25) 27(1.75,1.75) 28(1.75,2.25) 29(1.75,2.75)
  oval 0.3x0.8 smd mask+0.07: 13(-1,-3.5) 14(-0.5,-3.5) 15(0,-3.5) 16(0.5,-3.5) 17(1,-3.5) 30(1,3.5) 31(0.5,3.5) 32(0,3.5) 33(-0.5,3.5) 34(-1,3.5)
  rect 2.2x5.7 smd mask+0.07: 35(0,0)
  silkscreen extent -2.83,-3.6 1.85,3.6, body extent -1.83,-3.57 1.83,3.58, height 1
TP_HOLE [mil] "Bare wire test point hole"
  round 45 hole 25: 1(0,0)
TP_SMT_38mil [mil] "38 mil round test point, SMT"
  round 38 smd: 1(0,0)
TSOP65P640-16AN [mm] "TSOP, 16-Leads, Body 5x4.4mm, Pitch 0.65mm, IPC Medium Density"
  oval 1.7x0.35 smd: 1(-2.85,2.275) 2(-2.85,1.625) 3(-2.85,0.975) 4(-2.85,0.325) 5(-2.85,-0.325) 6(-2.85,-0.975) 7(-2.85,-1.625) 8(-2.85,-2.275) 9(2.85,-2.275) 10(2.85,-1.625) 11(2.85,-0.975) 12(2.85,-0.325) 13(2.85,0.325) 14(2.85,0.975) 15(2.85,1.625) 16(2.85,2.275)
  silkscreen extent -2.97,-2.55 1.6,3.12, body extent -2.25,-2.55 2.25,2.55, height 1.1
TSQFP50P900X900-48N [mm] "Thin QFP, 48-Leads, Body 7x7mm, Pitch 0.5mm, IPC Medium Density"
  oval 1.8x0.3 smd: 1(-4.05,2.75) 2(-4.05,2.25) 3(-4.05,1.75) 4(-4.05,1.25) 5(-4.05,0.75) 6(-4.05,0.25) 7(-4.05,-0.25) 8(-4.05,-0.75) 9(-4.05,-1.25) 10(-4.05,-1.75) 11(-4.05,-2.25) 12(-4.05,-2.75) 25(4.05,-2.75) 26(4.05,-2.25) 27(4.05,-1.75) 28(4.05,-1.25) 29(4.05,-0.75) 30(4.05,-0.25) 31(4.05,0.25) 32(4.05,0.75) 33(4.05,1.25) 34(4.05,1.75) 35(4.05,2.25) 36(4.05,2.75)
  oval 0.3x1.8 smd: 13(-2.75,-4.05) 14(-2.25,-4.05) 15(-1.75,-4.05) 16(-1.25,-4.05) 17(-0.75,-4.05) 18(-0.25,-4.05) 19(0.25,-4.05) 20(0.75,-4.05) 21(1.25,-4.05) 22(1.75,-4.05) 23(2.25,-4.05) 24(2.75,-4.05) 37(2.75,4.05) 38(2.25,4.05) 39(1.75,4.05) 40(1.25,4.05) 41(0.75,4.05) 42(0.25,4.05) 43(-0.25,4.05) 44(-0.75,4.05) 45(-1.25,4.05) 46(-1.75,4.05) 47(-2.25,4.05) 48(-2.75,4.05)
  silkscreen extent -4.17,-2.75 2.75,3.57, body extent -3.5,-3.5 3.5,3.5, height 1.6
TSSOP50P640-44N [mm] "TSSOP, 44-Leads, Body 11x4.4mm, Pitch 0.5mm, IPC Medium Density"
  oval 1.75x0.3 smd: 1(-2.775,5.25) 2(-2.775,4.75) 3(-2.775,4.25) 4(-2.775,3.75) 5(-2.775,3.25) 6(-2.775,2.75) 7(-2.775,2.25) 8(-2.775,1.75) 9(-2.775,1.25) 10(-2.775,0.75) 11(-2.775,0.25) 12(-2.775,-0.25) 13(-2.775,-0.75) 14(-2.775,-1.25) 15(-2.775,-1.75) 16(-2.775,-2.25) 17(-2.775,-2.75) 18(-2.775,-3.25) 19(-2.775,-3.75) 20(-2.775,-4.25) 21(-2.775,-4.75) 22(-2.775,-5.25) 23(2.775,-5.25) 24(2.775,-4.75) 25(2.775,-4.25) 26(2.775,-3.75) 27(2.775,-3.25) 28(2.775,-2.75) 29(2.775,-2.25) 30(2.775,-1.75) 31(2.775,-1.25) 32(2.775,-0.75) 33(2.775,-0.25) 34(2.775,0.25) 35(2.775,0.75) 36(2.775,1.25) 37(2.775,1.75) 38(2.775,2.25) 39(2.775,2.75) 40(2.775,3.25) 41(2.775,3.75) 42(2.775,4.25) 43(2.775,4.75) 44(2.775,5.25)
  silkscreen extent -2.9,-5.7 1.5,6.08, body extent -2.25,-5.7 2.25,5.7, height 1.2

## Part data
C100 C101 C102 C103 C104 C109 C112 C113 C114 C115 C116 C117 C118 C200 C201 C202 C203 C204 C205 C206 C207 C208 C209 C210 C211 C212 C213 C214 C215 C216 C217 C218 C219 C220 C221 C222 C223 C224 C225 C300 C301 C302 C303 C304 C305 C306 C307 C308 C309 C310 C311 C312 C313 C314 C315 C316 C317 C318 C319 C320 C321 C322 C323 C324 C325 C326: library part "Cap Semi", "Capacitor (Semiconductor SIM Model)"
C108: library part "Cap Pol3", "Taiyo Yuden PAS414HR-VA5R"
C110 C111: library part "CAP NP"
D100 D101 D200 D201 D202 D308: library part "D Schottky", "Schottky Diode"
D300 D301 D307: library part "Diode 1N4148", "Silicon diode"
D302 D303 D304 D305 D306: library part LED2, "Typical RED, GREEN, YELLOW, AMBER GaAs LED"
F300: library part "Fuse Thermal", "Thermal Fuse"
J100: library part SATA_22P_HEADER, "SATA+Power connector"
J101: library part "Header 5", "Header, 5-Pin"
J102 J103 J104 J105 J300 J301 TP100 TP101 TP102 TP103 TP104 TP105 TP106 TP107: library part CON1, "Connector"
JP200: library part PWR2.5, "Low Voltage Power Supply Connector"
L101 L200 L200B: library part "Inductor Iron", "Magnetic-Core Inductor"
P101 P102: library part "Header 2", "Header, 2-Pin"
P300: library part "Header 4", "Classic PC hard drive power connector, RA"
P301: library part "Header 5", "JST S4B-XH-A 2.5mm RA connector, stuffed in 5-pin slot, high pin aligned"
P302 P303: library part "Header 3", "Header, 3-Pin"
Q100 Q203 Q205 Q206 Q301: "Singre P-channel FET, 8A, 30V"
Q101 Q102 Q103 Q201 Q202 Q204 Q304: library part MOSFET-N, "N-Channel MOSFET"
Q200: library part MOSFET-P, "P-Channel MOSFET"
Q302 Q303: "Single N-channel FET, 11A, 30V"
R100 R101 R102 R103 R104 R105 R106 R107 R108 R109 R110 R111 R112 R113 R114 R115 R116 R117 R118 R119 R120 R121 R200 R201 R202 R203 R204 R205 R206 R207 R208 R209 R211 R213 R214 R215 R216 R217 R218 R219 R220 R221 R222 R223 R224 R225 R226 R300 R301 R303 R304 R305 R306 R307 R308 R309 R310 R311 R312 R313 R314 R315 R316 R317 R318 R319 R320 R321 R322 R323 R324 R325 R326 R327 R328 R329 R330 R331 R332 R333 R334 R335 R336 R337 R338 R339: library part Res1, "Resistor"
R210 R212 R302: library part RES_4TERM
SW100 SW101 SW300 SW301: library part "Header 4", "Chi Fung TS-1187A"
U100: library part STM32F103C8T6, "32-bit ARM Coretex high performance microcontroller"
U101: library part DAC081C81CIMK, "Single 8-bit DAC for I2C bus"
U102: "28V, 0.5A step-down converter with sleep mode"
U200: "SMBus-controlled battery charger with integrated FETs"
U300: library part bq77PL157A, "Voltage protection for 3-series to 6-series Li batteries"
U301: "SBS 1.1-Compliant Gas Gauge and Protection with Impedance Track (TM)"
U302: library part NTMFS4841N, "N channel power MOSFET, 30V, 57A SO-8FL"
Y100: library part XTAL, "Crystal Oscillator"

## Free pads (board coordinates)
  round 2 hole 2.9 unplated mask+1.5: 0(17.5,19) 0(40,38) 0(60,3) 2(118,3)
  round 2 hole 2.7 unplated mask+1.6: 0(118,38)
  rect 0.203x0.051 on Top Overlay: 1(44.828,10.101) 1(45.793,11.726) 1(45.844,14.114) 1(45.945,14.266) 1(46.25,13.454) 1(46.403,9.085) 1(47.063,13.149) 1(47.215,11.676) 1(47.215,13.962) 1(47.317,14.114) 1(47.368,14.165) 1(47.419,14.266) 1(47.469,14.317) 1(47.52,14.47) 1(47.571,13.504) 1(47.571,14.52) 1(47.622,13.555) 1(47.673,13.606) 1(47.723,13.657) 1(47.977,14.012) 1(47.977,14.063) 1(48.028,14.114) 1(48.079,14.216) 1(48.13,10.202) 1(48.13,14.266) 1(48.13,14.317) 1(49.298,13.911) 1(49.501,14.368) 1(50.06,14.673) 1(50.213,12.844) 1(50.213,14.52) 1(50.263,13.962) 1(50.314,14.012) 1(50.314,14.825) 1(50.365,14.063) 1(50.416,14.114) 1(50.416,14.724) 1(50.467,14.673) 1(50.873,11.676) 1(50.924,11.726) 1(50.924,13.301) 1(50.975,11.828) 1(51.025,14.266) 1(51.076,13.403) 1(51.127,14.114) 1(51.279,12.488) 1(51.279,13.555) 1(51.33,13.606) 1(51.381,13.657) 1(51.432,13.708) 1(51.483,13.758) 1(51.533,13.454) 1(51.533,13.809) 1(51.584,13.86) 1(51.635,13.911) 1(51.686,13.962) 1(51.838,13.2) 1(51.94,9.745) 1(51.991,11.726) 1(52.397,9.745)
  rect 0.254x0.051 on Top Overlay: 1(44.853,10.152) 1(44.904,10.202) 1(44.955,10.253) 1(44.955,13.352) 1(45.006,10.304) 1(45.006,13.403) 1(45.056,10.355) 1(45.107,10.406) 1(45.107,13.454) 1(45.158,10.456) 1(45.209,13.504) 1(45.26,10.609) 1(45.26,13.555) 1(45.31,10.66) 1(45.361,13.606) 1(45.412,13.657) 1(45.463,13.708) 1(45.514,13.758) 1(45.564,13.809) 1(45.717,13.962) 1(45.768,14.012) 1(45.818,11.676) 1(45.818,14.063) 1(45.869,14.165) 1(45.92,13.809) 1(45.92,14.216) 1(45.971,14.317) 1(46.072,13.708) 1(46.123,13.657) 1(46.174,13.606) 1(46.225,13.504) 1(46.225,13.555) 1(46.428,9.136) 1(46.58,12.793) 1(47.139,13.2) 1(47.241,13.25) 1(47.292,11.625) 1(47.292,13.301) 1(47.342,11.574) 1(47.393,11.523) 1(47.393,13.352) 1(47.444,13.403) 1(47.495,13.454) 1(47.546,14.673) 1(47.596,14.571) 1(47.596,14.622) 1(48.054,14.165) 1(48.155,10.253) 1(48.155,14.368) 1(48.917,11.168) 1(48.968,11.218) 1(49.019,9.085) 1(49.019,14.165) 1(49.222,14.012) 1(49.273,13.962) 1(49.273,14.571) 1(49.324,13.25) 1(49.425,14.47) 1(49.476,14.419) 1(49.679,10.456) 1(49.882,13.657) 1(49.933,13.708) 1(50.035,13.758) 1(50.086,13.809) 1(50.136,13.86) 1(50.136,14.622) 1(50.187,13.911) 1(50.187,14.571) 1(50.695,10.66) 1(50.746,10.914) 1(50.746,10.964) 1(50.746,11.015) 1(50.746,11.066) 1(50.746,11.117) 1(50.746,11.168) 1(50.746,11.218) 1(50.949,11.777) 1(51,11.879) 1(51,13.352) 1(51.051,11.93) 1(51.152,13.454) 1(51.203,13.504) 1(51.559,10.355) 1(51.61,13.403) 1(51.813,14.724) 1(51.914,14.622) 1(51.965,9.796) 1(52.422,9.593) 1(52.422,9.644) 1(52.422,9.694)
  rect 0.102x0.051 on Top Overlay: 1(44.879,13.301) 1(45.082,14.47) 1(45.742,11.777) 1(45.996,14.52) 1(46.961,13.708) 1(48.892,11.117) 1(49.146,13.454) 1(49.146,13.504) 1(49.603,10.406) 1(50.009,14.724) 1(50.263,14.419) 1(50.568,14.317) 1(50.975,14.317) 1(51.838,13.149) 1(51.94,9.694)
  rect 0.305x0.051 on Top Overlay: 1(45.183,10.507) 1(45.234,10.558) 1(45.336,10.71) 1(45.387,10.761) 1(45.437,10.812) 1(45.437,10.863) 1(45.488,10.914) 1(45.539,11.015) 1(45.59,11.066) 1(45.641,11.168) 1(45.996,13.758) 1(46.047,14.368) 1(46.606,9.593) 1(46.606,9.644) 1(46.606,9.694) 1(46.606,9.745) 1(46.606,9.796) 1(46.606,9.847) 1(46.606,9.898) 1(46.606,9.948) 1(46.606,9.999) 1(46.606,10.05) 1(46.606,10.101) 1(46.606,10.152) 1(46.606,10.202) 1(46.606,10.253) 1(46.606,10.304) 1(46.606,10.355) 1(46.606,10.406) 1(46.606,10.456) 1(46.606,10.507) 1(46.606,10.558) 1(46.606,10.609) 1(46.606,10.66) 1(46.606,10.71) 1(46.606,10.761) 1(46.606,10.812) 1(46.606,10.863) 1(46.606,10.914) 1(46.606,10.964) 1(46.606,11.015) 1(46.606,11.066) 1(46.606,11.117) 1(46.606,11.168) 1(46.606,11.218) 1(46.606,11.269) 1(46.606,11.32) 1(46.606,11.371) 1(46.606,11.422) 1(46.606,11.472) 1(46.606,11.523) 1(46.606,11.574) 1(46.606,11.625) 1(46.606,11.676) 1(46.606,11.726) 1(46.606,11.777) 1(46.606,11.828) 1(46.606,11.879) 1(46.606,11.93) 1(46.606,11.98) 1(46.606,12.031) 1(46.606,12.082) 1(46.606,12.133) 1(46.606,12.184) 1(46.606,12.234) 1(46.606,12.285) 1(46.606,12.336) 1(46.606,12.387) 1(46.606,12.438) 1(46.606,12.488) 1(46.606,12.539) 1(47.419,11.472) 1(47.469,11.422) 1(47.52,11.371) 1(47.876,13.809) 1(47.876,13.86) 1(48.13,10.304) 1(49.044,11.269) 1(49.095,11.32) 1(49.197,14.063) 1(49.298,11.472) 1(49.603,11.777) 1(49.603,13.454) 1(49.654,13.504) 1(49.705,10.507) 1(49.705,10.558) 1(49.705,10.609) 1(49.705,10.66) 1(49.705,10.812) 1(49.705,10.863) 1(49.705,10.914) 1(49.705,10.964) 1(49.705,11.015) 1(49.705,11.066) 1(49.705,11.117) 1(49.705,11.168) 1(49.705,11.218) 1(49.705,11.269) 1(49.705,11.32) 1(49.705,11.371) 1(49.705,11.422) 1(49.705,11.472) 1(49.755,13.555) 1(49.806,13.606) 1(50.365,14.774) 1(50.467,9.999) 1(50.517,10.101) 1(50.568,10.202) 1(50.568,10.253) 1(50.619,10.304) 1(50.619,10.355) 1(50.619,10.406) 1(50.67,10.456) 1(50.67,10.507) 1(50.67,10.558) 1(50.67,10.609) 1(50.721,10.812) 1(50.721,10.863) 1(50.771,11.269) 1(50.771,11.32) 1(50.771,11.371) 1(50.771,11.422) 1(50.771,11.472) 1(51.076,9.593) 1(51.076,9.644) 1(51.076,9.694) 1(51.076,9.745) 1(51.076,9.796) 1(51.076,9.847) 1(51.076,9.898) 1(51.076,9.948) 1(51.076,9.999) 1(51.076,10.05) 1(51.076,10.101) 1(51.076,10.152) 1(51.076,10.202) 1(51.076,10.253) 1(51.076,10.304) 1(51.076,10.355) 1(51.076,10.406) 1(51.076,10.456) 1(51.076,10.507) 1(51.076,10.558) 1(51.076,10.609) 1(51.076,10.66) 1(51.076,11.98) 1(51.127,12.031) 1(51.279,12.438) 1(51.838,13.25) 1(51.838,14.114) 1(51.838,14.165) 1(51.94,9.847) 1(51.94,9.898) 1(51.991,10.558) 1(51.991,10.609) 1(51.991,10.66) 1(51.991,10.812) 1(51.991,10.863) 1(51.991,10.914) 1(51.991,10.964) 1(51.991,11.015) 1(51.991,11.066) 1(51.991,11.117) 1(51.991,11.168) 1(51.991,11.218) 1(51.991,11.269) 1(51.991,11.32) 1(51.991,11.371) 1(51.991,11.422) 1(51.991,11.472) 1(51.991,11.676) 1(52.448,14.317)
  rect 0.152x0.051 on Top Overlay: 1(45.26,14.266) 1(46.276,13.403) 1(46.53,12.844) 1(46.987,13.758) 1(47.038,13.809) 1(47.088,13.86) 1(47.139,13.911) 1(47.19,11.726) 1(47.241,14.012) 1(47.393,14.216) 1(47.495,14.724) 1(48.155,10.152) 1(48.155,14.52) 1(49.324,13.2) 1(49.527,14.317) 1(50.187,12.895) 1(50.238,14.47) 1(50.441,14.165) 1(50.492,14.216) 1(50.492,14.622) 1(50.543,14.266) 1(51.508,10.406) 1(51.914,10.507) 1(51.914,13.403) 1(51.914,13.454) 1(51.914,13.504) 1(51.914,13.555) 1(51.914,13.606) 1(51.914,13.657) 1(51.914,13.708) 1(51.914,13.758) 1(51.914,13.809) 1(51.914,13.86) 1(51.914,13.911) 1(51.914,13.962) 1(51.914,14.317) 1(51.914,14.368) 1(51.914,14.419) 1(51.914,14.47) 1(51.914,14.52) 1(51.914,14.571) 1(51.965,11.777) 1(52.422,9.796) 1(52.422,9.847) 1(52.422,9.898) 1(52.422,9.948) 1(52.422,9.999) 1(52.422,10.05) 1(52.422,10.101) 1(52.422,10.152) 1(52.422,10.202)
  rect 0.406x0.051 on Top Overlay: 1(45.285,14.317) 1(45.691,11.269) 1(45.742,11.371) 1(45.793,11.422) 1(45.945,14.47) 1(45.996,9.542) 1(46.453,9.237) 1(46.657,12.641) 1(47.571,14.368) 1(47.673,11.218) 1(47.723,11.168) 1(47.774,11.117) 1(47.825,11.066) 1(47.825,13.708) 1(47.825,13.911) 1(47.876,10.964) 1(47.876,13.758) 1(48.13,10.406) 1(48.13,10.456) 1(48.13,10.507) 1(49.349,13.301) 1(49.959,9.491) 1(50.06,9.542) 1(50.06,12.438) 1(50.111,9.593) 1(50.111,12.488) 1(50.162,9.644) 1(50.162,12.539) 1(50.263,12.742) 1(51.127,9.491) 1(51.178,9.44) 1(51.279,12.387) 1(51.737,10.202) 1(51.787,10.152) 1(51.787,13.352) 1(51.787,14.012) 1(51.838,10.101) 1(51.889,9.999) 1(51.889,10.05) 1(52.448,9.491)
  rect 0.762x0.051 on Top Overlay: 1(45.463,14.368) 1(46.377,9.39)
  rect 0.356x0.051 on Top Overlay: 1(45.514,10.964) 1(45.615,11.117) 1(45.666,11.218) 1(45.717,11.32) 1(45.717,13.911) 1(45.818,11.625) 1(46.428,9.186) 1(46.58,9.542) 1(46.631,12.59) 1(46.631,12.742) 1(47.596,11.32) 1(47.596,14.012) 1(47.647,11.269) 1(48.155,10.355) 1(49.07,14.114) 1(49.171,11.371) 1(49.222,11.422) 1(49.324,14.52) 1(49.578,11.726) 1(49.628,11.828) 1(49.679,11.879) 1(49.73,11.93) 1(49.781,11.98) 1(49.781,12.031) 1(49.832,12.082) 1(49.882,12.133) 1(49.882,12.184) 1(49.933,12.234) 1(50.035,12.387) 1(50.238,9.694) 1(50.238,12.793) 1(50.289,9.745) 1(50.34,9.796) 1(50.34,9.847) 1(50.39,9.898) 1(50.441,9.948) 1(50.492,10.05) 1(50.543,10.152) 1(51.102,9.542) 1(51.152,12.082) 1(51.203,12.133) 1(51.61,10.304) 1(51.66,10.253) 1(51.813,13.301) 1(51.813,14.063) 1(51.864,14.673) 1(51.914,9.948) 1(52.422,9.542)
  rect 1.118x0.051 on Top Overlay: 1(45.59,14.419)
  rect 0.508x0.051 on Top Overlay: 1(45.742,13.86) 1(45.844,11.472) 1(45.844,11.523) 1(47.419,14.063) 1(47.774,13.962) 1(49.247,9.186) 1(49.349,13.352) 1(49.4,9.237) 1(49.552,9.288) 1(50.263,12.692) 1(51.33,12.234) 1(52.448,9.44)
  rect 0.457x0.051 on Top Overlay: 1(45.869,11.574) 1(46.682,12.692) 1(47.85,11.015) 1(47.901,10.914) 1(47.952,10.863) 1(48.003,10.761) 1(48.003,10.812) 1(48.054,10.66) 1(48.054,10.71) 1(48.104,10.558) 1(48.104,10.609) 1(49.12,9.136) 1(49.578,11.676) 1(49.679,9.339) 1(49.781,9.39) 1(49.882,9.44) 1(50.187,12.59) 1(50.238,12.641) 1(51.254,12.184)
  rect 0.965x0.051 on Top Overlay: 1(46.276,9.491)
  rect 0.914x0.051 on Top Overlay: 1(46.301,9.44) 1(47.876,14.419)
  rect 0.61x0.051 on Top Overlay: 1(46.403,9.339) 1(48.028,14.47) 1(49.4,13.403) 1(51.279,14.165)
  rect 0.559x0.051 on Top Overlay: 1(46.428,9.288)
  rect 0.051x0.051 on Top Overlay: 1(47.038,13.098) 1(47.19,11.777) 1(50.492,14.571) 1(50.898,13.25) 1(51.254,12.539) 1(51.508,13.504)
  rect 1.727x0.051 on Top Overlay: 1(50.67,12.336) 1(51.838,9.39)
  rect 2.997x0.051 on Top Overlay: 1(50.695,11.523) 1(50.746,11.574)
  rect 1.778x0.051 on Top Overlay: 1(50.695,12.285) 1(51.813,14.216)
  rect 2.946x0.051 on Top Overlay: 1(50.771,11.625)
  rect 2.591x0.051 on Top Overlay: 1(50.848,10.71) 1(50.848,10.761)
  rect 1.372x0.051 on Top Overlay: 1(51.813,9.186)
  rect 1.473x0.051 on Top Overlay: 1(51.813,9.237)
  rect 1.676x0.051 on Top Overlay: 1(51.813,9.339)
  rect 1.626x0.051 on Top Overlay: 1(51.838,9.288)
  rect 1.27x0.051 on Top Overlay: 1(52.016,14.266)
  rect 2.489x0.051 on Bottom Overlay: 1(57.977,12.186) 1(57.977,12.237) 1(57.977,12.287) 1(60.263,14.573)
  rect 2.54x0.051 on Bottom Overlay: 1(58.002,11.932) 1(58.002,11.983) 1(58.002,12.033) 1(58.002,12.084) 1(58.002,12.135) 1(58.002,12.338) 1(58.002,12.389) 1(58.002,12.44) 1(58.002,12.491) 1(58.002,12.541) 1(58.104,12.745) 1(62.422,12.745) 1(62.523,11.983) 1(62.523,12.033) 1(62.523,12.084) 1(62.523,12.135) 1(62.523,12.186) 1(62.523,12.237) 1(62.523,12.287) 1(62.523,12.338) 1(62.523,12.389) 1(62.523,12.44) 1(62.523,12.491) 1(62.523,12.541)
  rect 2.591x0.051 on Bottom Overlay: 1(58.027,11.83) 1(58.027,11.881) 1(58.027,12.592) 1(58.027,12.643) 1(58.027,12.694) 1(58.078,11.779) 1(62.447,11.779) 1(62.498,11.83) 1(62.498,11.881) 1(62.498,11.932) 1(62.498,12.592) 1(62.498,12.643)
  rect 0.102x0.051 on Bottom Overlay: 1(58.104,15.031) 1(59.17,9.798) 1(61.355,9.798) 1(62.422,15.031)
  rect 0.152x0.051 on Bottom Overlay: 1(58.129,9.493) 1(62.396,9.493)
  rect 0.254x0.051 on Bottom Overlay: 1(58.129,9.544) 1(58.129,14.98) 1(59.145,9.849) 1(61.38,9.849) 1(62.396,9.544) 1(62.396,14.98)
  rect 0.356x0.051 on Bottom Overlay: 1(58.129,9.595) 1(58.129,14.929) 1(59.094,9.9) 1(61.431,9.9) 1(62.396,14.929)
  rect 0.457x0.051 on Bottom Overlay: 1(58.129,14.878)
  rect 0.508x0.051 on Bottom Overlay: 1(58.154,9.646) 1(62.371,9.646) 1(62.371,14.878)
  rect 0.61x0.051 on Bottom Overlay: 1(58.154,9.697) 1(58.154,14.827) 1(62.371,14.827)
  rect 0.711x0.051 on Bottom Overlay: 1(58.154,14.777)
  rect 0.762x0.051 on Bottom Overlay: 1(58.18,9.747) 1(62.345,9.747) 1(62.345,14.777)
  rect 0.864x0.051 on Bottom Overlay: 1(58.18,9.798) 1(58.18,14.726) 1(60.263,15.793) 1(62.345,9.798) 1(62.345,14.726)
  rect 0.965x0.051 on Bottom Overlay: 1(58.18,14.675) 1(60.263,15.64) 1(60.263,15.691) 1(60.263,15.742) 1(62.345,14.675)
  rect 1.016x0.051 on Bottom Overlay: 1(58.205,9.849) 1(60.237,15.589) 1(62.32,9.849)
  rect 1.118x0.051 on Bottom Overlay: 1(58.205,9.9) 1(58.205,14.624) 1(60.237,15.285) 1(62.32,9.9) 1(62.32,14.624)
  rect 2.337x0.051 on Bottom Overlay: 1(58.205,11.729) 1(58.967,13.253) 1(62.32,11.729)
  rect 1.219x0.051 on Bottom Overlay: 1(58.205,14.573) 1(60.237,15.031) 1(62.32,14.573)
  rect 2.286x0.051 on Bottom Overlay: 1(58.231,12.795) 1(61.533,13.253) 1(62.244,12.795)
  rect 2.134x0.051 on Bottom Overlay: 1(58.358,11.678) 1(58.866,13.202) 1(61.66,13.202) 1(62.168,11.678)
  rect 1.829x0.051 on Bottom Overlay: 1(58.408,10.052) 1(58.51,10.306) 1(58.561,10.408) 1(58.561,11.576) 1(58.561,12.897) 1(58.612,11.525) 1(58.612,12.948) 1(58.815,10.967) 1(58.815,11.017) 1(61.71,10.967) 1(61.71,11.017) 1(61.863,12.999) 1(61.914,10.459) 1(61.914,11.525) 1(61.914,11.576) 1(61.914,12.948) 1(61.964,10.357) 1(61.964,10.408) 1(61.964,12.897) 1(62.015,10.306) 1(62.117,10.052)
  rect 1.93x0.051 on Bottom Overlay: 1(58.408,10.103) 1(58.713,11.424) 1(58.713,13.1) 1(58.815,11.119) 1(58.815,11.17) 1(61.71,11.119) 1(61.71,11.17) 1(61.812,11.424) 1(61.812,13.1) 1(61.863,11.475) 1(62.117,10.103)
  rect 2.032x0.051 on Bottom Overlay: 1(58.408,12.846) 1(58.764,11.322) 1(58.815,11.221) 1(58.815,11.271) 1(61.71,11.221) 1(61.71,11.271) 1(61.71,11.322) 1(62.117,12.846)
  rect 1.676x0.051 on Bottom Overlay: 1(58.434,9.951) 1(58.789,10.814)
  rect 1.778x0.051 on Bottom Overlay: 1(58.434,10.001) 1(58.586,10.459) 1(58.637,10.509) 1(58.637,10.56) 1(58.688,10.611) 1(58.739,10.713) 1(61.787,10.713) 1(61.837,10.611) 1(61.888,10.509) 1(61.888,10.56) 1(62.091,10.001)
  rect 1.88x0.051 on Bottom Overlay: 1(58.434,10.154) 1(58.434,10.205) 1(58.485,10.255) 1(58.535,10.357) 1(58.535,11.627) 1(58.637,11.475) 1(58.637,12.999) 1(58.688,13.049) 1(58.789,11.068) 1(61.685,11.068) 1(61.837,13.049) 1(61.99,11.627) 1(62.041,10.205) 1(62.041,10.255) 1(62.091,10.154)
  rect 1.727x0.051 on Bottom Overlay: 1(58.713,10.662) 1(58.764,10.763) 1(58.815,10.865) 1(58.815,10.916) 1(60.237,14.726) 1(61.71,10.814) 1(61.71,10.865) 1(61.71,10.916) 1(61.761,10.763) 1(61.812,10.662) 1(62.066,9.951)
  rect 1.981x0.051 on Bottom Overlay: 1(58.739,11.373) 1(58.789,13.151) 1(60.263,14.675) 1(61.736,13.151) 1(61.787,11.373)
  rect 4.674x0.051 on Bottom Overlay: 1(60.237,13.71)
  rect 4.877x0.051 on Bottom Overlay: 1(60.237,13.862)
  rect 5.08x0.051 on Bottom Overlay: 1(60.237,14.015)
  rect 4.826x0.051 on Bottom Overlay: 1(60.263,13.303) 1(60.263,13.354) 1(60.263,13.811)
  rect 4.724x0.051 on Bottom Overlay: 1(60.263,13.405) 1(60.263,13.456) 1(60.263,13.761)
  rect 4.623x0.051 on Bottom Overlay: 1(60.263,13.507) 1(60.263,13.557) 1(60.263,13.608) 1(60.263,13.659)
  rect 4.928x0.051 on Bottom Overlay: 1(60.263,13.913)
  rect 5.029x0.051 on Bottom Overlay: 1(60.263,13.964)
  rect 5.131x0.051 on Bottom Overlay: 1(60.263,14.065)
  rect 5.232x0.051 on Bottom Overlay: 1(60.263,14.116)
  rect 5.334x0.051 on Bottom Overlay: 1(60.263,14.167) 1(60.263,14.218)
  rect 5.436x0.051 on Bottom Overlay: 1(60.263,14.269) 1(60.263,14.523)
  rect 5.537x0.051 on Bottom Overlay: 1(60.263,14.319) 1(60.263,14.37) 1(60.263,14.472)
  rect 5.639x0.051 on Bottom Overlay: 1(60.263,14.421)
  rect 2.184x0.051 on Bottom Overlay: 1(60.263,14.624)
  rect 1.473x0.051 on Bottom Overlay: 1(60.263,14.777)
  rect 1.27x0.051 on Bottom Overlay: 1(60.263,14.827) 1(60.263,14.878) 1(60.263,14.929) 1(60.263,14.98)
  rect 1.168x0.051 on Bottom Overlay: 1(60.263,15.081) 1(60.263,15.132) 1(60.263,15.183) 1(60.263,15.234)
  rect 1.067x0.051 on Bottom Overlay: 1(60.263,15.335) 1(60.263,15.386) 1(60.263,15.437) 1(60.263,15.488) 1(60.263,15.539)
  rect 0.66x0.051 on Bottom Overlay: 1(62.345,9.697)
  rect 0.406x0.051 on Bottom Overlay: 1(62.371,9.595)
  rect 2.642x0.051 on Bottom Overlay: 1(62.472,12.694)

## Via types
v1: diameter 0.508, hole 0.254, Top Layer to Bottom Layer, tented both sides, 187 vias
v2: diameter 0.762, hole 0.381, Top Layer to Bottom Layer, tented both sides, 155 vias
v3: diameter 0.66, hole 0.33, Top Layer to Bottom Layer, tented top, 9 vias
v4: diameter 0.5, hole 0.2, Top Layer to Bottom Layer, 3 vias
v5: diameter 0.66, hole 0.33, Top Layer to Bottom Layer, tented both sides, 1 vias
